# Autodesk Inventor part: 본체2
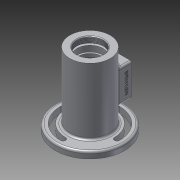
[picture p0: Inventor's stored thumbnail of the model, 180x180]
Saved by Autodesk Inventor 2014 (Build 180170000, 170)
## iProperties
Created: 2017-05
Part Number: 본체2
Material: 알루미늄 6061
Document SubType Name: Modeling
Designer: Administrator
Density: 2.71 g/cm^3
Appearance: 알루미늄 - 평지
Mass: 679.861 g
Surface Area: 618.501 cm^2
Volume: 250.871 cm^3
Author: Administrator
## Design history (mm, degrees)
sketch "스케치1"
  geometry: C1 r 53 at (0, 0); 1 further point
  constraints: 1 centre point, 1 coincident
  dimensions: "d0" = 106 diameter of C1
extrude "돌출1" new body sketch "스케치1" distance "d1" = 10; taper "d2" = 0 deg
sketch "스케치2"
  geometry: C1 r 53 at (0, 0) reference; C2 r 31 at (0, 0)
  constraints: 1 centre point, 1 coincident
  dimensions: "d3" = 62 diameter of C2
extrude "돌출2" join sketch "스케치2" distance "d4" = 102; taper "d5" = 0 deg
sketch "스케치3"
  geometry: C1 r 31 at (0, 0) reference; 1 further point
  constraints: 1 coincident
hole "구멍1" sketch "스케치3" at (0, 0) diameter "d6" = 40.376; stored, may be unused: countersink angle "d10" = 90 deg, drill point angle "d12" = 0 deg; dims "d7" = 9, "d8" = 4, "d9" = 2, "d11" = 9
sketch "스케치4"
  geometry: C1 r 20.188 at (0, 0) reference; C2 r 24 at (0, 0)
  constraints: 1 centre point, 1 coincident
  dimensions: "d13" = 48 diameter of C2
extrude "돌출3" cut sketch "스케치4" distance "d14" = 3; taper "d15" = 0 deg
sketch "스케치5"
  geometry: C1 r 24 at (0, 0) reference; C2 r 20 at (0, 0)
  constraints: 1 centre point, 1 coincident
  dimensions: "d16" = 40 diameter of C2
extrude "돌출4" cut sketch "스케치5" distance "d17" = 9; taper "d18" = 0 deg
sketch "스케치6"
  geometry: C1 r 20 at (0, 0) reference; C2 r 17.5 at (0, 0)
  constraints: 1 centre point, 1 coincident
  dimensions: "d19" = 35 diameter of C2
extrude "돌출5" cut sketch "스케치6" distance "d20" = 5; taper "d21" = 0 deg
sketch "스케치7"
  geometry: C1 r 17.5 at (0, 0) reference; C2 r 18.5 at (0, 0)
  constraints: 1 centre point, 1 coincident
  dimensions: "d22" = 37 diameter of C2
extrude "돌출6" cut sketch "스케치7" distance "d23" = 1.75; taper "d24" = 0 deg
sketch "스케치8"
  geometry: C1 r 18.5 at (0, 0) reference; C2 r 17.5 at (0, 0)
  constraints: 1 centre point, 1 coincident
  dimensions: "d25" = 35 diameter of C2
extrude "돌출7" cut sketch "스케치8" distance "d26" = 11; taper "d27" = 0 deg
sketch "스케치9"
  geometry: C1 r 17.5 at (0, 0) reference; C2 r 26 at (0, 0)
  constraints: 1 centre point, 1 coincident
  dimensions: "d28" = 52 diameter of C2
extrude "돌출8" cut sketch "스케치9" distance "d29" = 38; taper "d30" = 0 deg
sketch "스케치10"
  geometry: C1 r 26 at (0, 0) reference; C2 r 17.5 at (0, 0)
  constraints: 1 centre point, 1 coincident
  dimensions: "d31" = 35 diameter of C2
extrude "돌출9" cut sketch "스케치10" distance "d32" = 11; taper "d33" = 0 deg
sketch "스케치11"
  geometry: C1 r 17.5 at (0, 0) reference; C2 r 16.5 at (0, 0)
  constraints: 1 centre point, 1 coincident
  dimensions: "d34" = 33 diameter of C2
extrude "돌출10" cut sketch "스케치11" distance "d35" = 5; taper "d36" = 0 deg
sketch "스케치12"
  geometry: C1 r 16.5 at (0, 0) reference; C2 r 10 at (0, 0)
  constraints: 1 centre point, 1 coincident
  dimensions: "d37" = 20 diameter of C2
extrude "돌출11" cut sketch "스케치12" distance "d38" = 2.7; taper "d39" = 0 deg
sketch "스케치13"
  geometry: C1 r 10 at (0, 0) reference; C2 r 12.5 at (0, 0)
  constraints: 1 centre point, 1 coincident
  dimensions: "d40" = 25 diameter of C2
extrude "돌출12" cut sketch "스케치13" distance "d41" = 7.3; taper "d42" = 0 deg
sketch "스케치15"
  geometry: C1 r 53 at (0, 0) reference; C2 r 31 at (0, 0)
  constraints: 1 centre point, 1 coincident
  dimensions: "d43" = 62 diameter of C2
extrude "돌출13" join sketch "스케치15" distance "d44" = 3; taper "d45" = 0 deg
sketch "스케치14"
  geometry: L1 (-31, -3)-(31, -3) reference; L2 (22, -3)-(16, 11); L3 (16, 11)-(-16, 11); L4 (-16, 11)-(-22, -3); L5 (-53, 0)-(53, 0) reference; L6 (0, 0)-(0, -22.236); L7 (0, -3)-(0, 11); L8 (16, 11)-(0, 11); L9 (22, -3)-(0, -3)
  constraints: 14 end point, 3 perpendicular, 3 point on line, 2 midpoint, 1 parallel, 1 other
  dimensions: "d46" = 44 distance of L4.end L2.start; "d47" = 32 distance of L2.end L3.end; "d48" = 14 distance between parallel lines of L1 L3
revolve "회전1" sketch "스케치14" stored, may be unused: angle "d49" = 90 deg
chamfer "모따기1" distance "d50" = 0.7; stored, may be unused: second distance "d51" = 2, angle "d52" = 30 deg
sketch "스케치16"
  geometry: L1 (0, 0)-(60.484, 0); L2 (0, 0)-(0, 62.49); L3 (0, 0)-(-61.126, 0); L4 (0, 0)-(0, -60.725); C1 r 53 at (0, 0) reference; A1 r 41.5 centre (0, 0) between (0, 41.5) and (41.5, 0); A2 r 4 centre (0, 41.5) between (0, 37.5) and (0, 45.5); A3 r 4 centre (41.5, 0) between (45.5, 0) and (37.5, 0); A4 r 4 centre (0, -41.5) between (0, -45.5) and (0, -37.5); A5 r 4 centre (-41.5, 0) between (-45.5, 0) and (-37.5, 0); A6 r 45.5 centre (0, 0) between (0, -45.5) and (45.5, 0); A7 r 45.5 centre (0, 0) between (0, 45.5) and (-45.5, 0); A8 r 37.5 centre (0, 0) between (0, -37.5) and (37.5, 0); A9 r 37.5 centre (0, 0) between (0, 37.5) and (-37.5, 0)
  constraints: 20 point on circle, 9 centre point, 8 end point, 8 point on line, 3 coincident, 3 perpendicular, 1 horizontal
  dimensions: "d55" = 83 diameter of A1; "d56" = 4 radius of A2; "d57" = 4 radius of A3; "d58" = 4 radius of A4; "d60" = 8 diameter of A5
extrude "돌출14" cut sketch "스케치16" distance "d61" = 13; taper "d62" = 0 deg
node "작업 평면1"
sketch "스케치18"
  geometry: L1 (20, 81)-(-20, 81); L2 (-20, 81)-(-20, 31); L3 (-20, 31)-(20, 31); L4 (20, 31)-(20, 81); L5 (0, 0)-(0, 151.656); L6 (20, 81)-(-20, 31); L7 (0, 56)-(32.406, 56); L8 (31, 112)-(-31, 112) reference
  constraints: 14 end point, 3 parallel, 2 perpendicular, 1 horizontal, 1 midpoint, 1 point on line
  dimensions: "d65" = 56 distance between parallel lines of L8 L7; "d66" = 50 distance of L3.end L1.start; "d67" = 40 distance of L1.start L1.end
extrude "돌출15" join sketch "스케치18" stored distance "d68" = 13; taper "d69" = 0 deg
sketch "스케치19"
  geometry: L1 (-11, -40)-(11, -40); L2 (11, -40)-(11, -72); L3 (11, -72)-(-11, -72); L4 (-11, -72)-(-11, -40); L5 (0, 0)-(0, -131.195); L6 (0, -56)-(71.693, -56); L7 (-31, -112)-(31, -112) reference; L8 (11, -40)-(-11, -72)
  constraints: 14 end point, 3 parallel, 2 perpendicular, 1 horizontal, 1 midpoint, 1 point on line, 1 other
  dimensions: "d70" = 56 distance between parallel lines of L7 L6; "d71" = 22 distance of L2.end L3.end; "d72" = 32 distance of L1.end L2.end
extrude "돌출16" cut sketch "스케치19" stored distance "d73" = 13; taper "d74" = 0 deg
fillet "모깎기1" dims "d75" = 3
fillet "모깎기2" dims "d76" = 3
fillet "모깎기3" dims "d77" = 3
fillet "모깎기4" dims "d78" = 0.3
sketch "스케치20"
  geometry: L1 (20, -78)-(20, -34) reference; L2 (17, -31)-(-17, -31) reference; L3 (-15.5, -35.5)-(15.5, -35.5); L4 (15.5, -35.5)-(15.5, -76.5); L5 (15.5, -76.5)-(-15.5, -76.5); L6 (-15.5, -76.5)-(-15.5, -35.5); 9 further points
  constraints: 8 end point, 4 coincident, 4 midpoint, 2 parallel, 1 horizontal, 1 horizontal alignment, 1 perpendicular, 1 vertical alignment
  dimensions: "d79" = 31 distance of L3.start L3.end; "d80" = 41 distance of L3.end L4.end
hole "구멍2" sketch "스케치20" at (-15.5, -35.5), (15.5, -35.5), (15.5, -76.5), (-15.5, -76.5) diameter "d81" = 2.459; stored, may be unused: countersink angle "d85" = 90 deg, drill point angle "d87" = 118 deg; dims "d82" = 6, "d83" = 4, "d84" = 2, "d86" = 8
sketch "스케치21"
  geometry: L1 (0, 0)-(44, 0) reference; L2 (-34, -13)-(-34, -75) reference; 2 further points
  constraints: 1 other
  dimensions: "d88" = 56 distance from line of L2 point (22, -8); "d89" = 8 distance from line of point (22, -8) L1
feature "엠보싱1" sketch "스케치21" dims "d90" = 0.5, "d91" = 0
chamfer "모따기2" distance "d92" = 1; stored, may be unused: second distance "d93" = 2, angle "d94" = 30 deg
node "솔리드1"
other parameters: "d53" = 91, "d54" = 75, "d64" = 44
